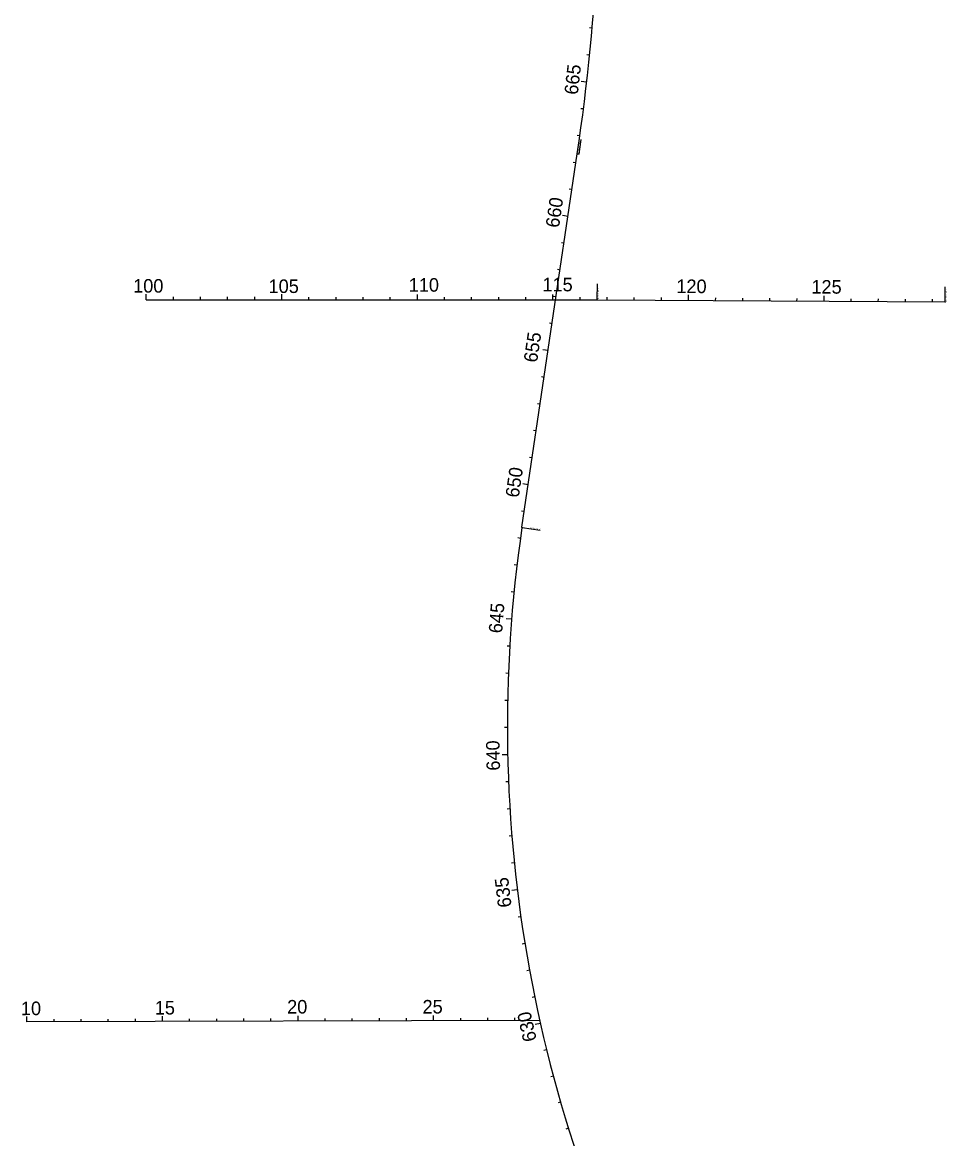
# Model space of a CAD drawing. Extents: x 448091 to 665917, y 1461380 to 1587607.
# Drawn here: x 474927 to 478337, y 1578644 to 1582760 of the extents above; entities that cross this region are included whole.
import ezdxf

# ---------------------------------------------------------------- set-up
doc = ezdxf.new("R2010")
doc.units = 0
for name, color, linetype in [('AttenuatorTM', 7, 'Continuous'), ('BillboardVeg', 7, 'Continuous'), ('BillboardZone', 7, 'Continuous'), ('BLSurvey_dp', 7, 'Continuous'), ('BLSurveyCntrl_ep', 7, 'Continuous'), ('BLSurveyField_ep', 7, 'Continuous'), ('BLSurveySymbl_ep', 7, 'Continuous'), ('BoxCulvert_ep', 7, 'Continuous')]:
    doc.layers.add(name, color=color, linetype=linetype)

msp = doc.modelspace()

# ---------------------------------------------------------------- linework, layer by layer
at = {"layer": 'AttenuatorTM'}
for p, q in [((476980.8, 1582273.8), (476988.8, 1582327.9)), ((476980.8, 1582273.8), (476974.7, 1582274.7)), ((477048, 1581737.8), (477048.1, 1581796.3)), ((478330.9, 1581729.9), (478331.3, 1581784.9)), ((476770.9, 1580898.1), (476836.7, 1580888.3))]:
    msp.add_line(p, q, dxfattribs=at)
for centre in [(476974, 1582274.8), (477048, 1581737.1), (478330.9, 1581729.1), (476770.1, 1580898.2)]:
    msp.add_circle(centre, 0.75, dxfattribs=at)
at = {"layer": 'BillboardVeg'}
msp.add_line((476770.1, 1580898.2), (476974, 1582274.8), dxfattribs=at)
for centre, radius, start, end in [((469060.2, 1583446.5), 8000, 351.57825, 2.73207), ((481716.2, 1580165.9), 5000, 171.5783, 209.1468)]:
    msp.add_arc(centre, radius, start, end, dxfattribs=at)
at = {"layer": 'BLSurvey_dp'}
for p, q in [((477028.9, 1582738.9), (477018.9, 1582739.8)), ((477019.4, 1582639.4), (477009.5, 1582640.4)), ((477008.7, 1582539.9), (476988.8, 1582542.2)), ((476996.7, 1582440.7), (476986.8, 1582441.9)), ((476983.6, 1582341.5), (476973.7, 1582342.9)), ((476969.2, 1582242.6), (476959.3, 1582244)), ((476954.5, 1582143.7), (476944.7, 1582145.1)), ((476939.9, 1582044.7), (476920.1, 1582047.7)), ((476925.3, 1581945.8), (476915.4, 1581947.3)), ((476910.6, 1581846.9), (476900.7, 1581848.4)), ((476896, 1581748), (476886.1, 1581749.4)), ((476881.3, 1581649), (476871.4, 1581650.5)), ((476866.7, 1581550.1), (476846.9, 1581553.1)), ((476852, 1581451.2), (476842.1, 1581452.7)), ((476837.4, 1581352.3), (476827.5, 1581353.7)), ((476822.7, 1581253.4), (476812.8, 1581254.8)), ((476808.1, 1581154.4), (476798.2, 1581155.9)), ((476793.4, 1581055.5), (476773.7, 1581058.4)), ((476778.8, 1580956.6), (476768.9, 1580958.1)), ((476764.3, 1580857.6), (476754.4, 1580859)), ((476751.5, 1580758.5), (476741.5, 1580759.7)), ((476740.6, 1580659.1), (476730.7, 1580660.1)), ((476731.7, 1580559.5), (476711.8, 1580561)), ((476724.9, 1580459.7), (476714.9, 1580460.3)), ((476720, 1580359.8), (476710, 1580360.2)), ((476717.1, 1580259.9), (476707.1, 1580260.1)), ((476716.2, 1580159.9), (476706.2, 1580159.9)), ((476717.4, 1580059.9), (476697.4, 1580059.5)), ((476720.5, 1579959.9), (476710.5, 1579959.5)), ((476725.6, 1579860.1), (476715.6, 1579859.5)), ((476732.7, 1579760.3), (476722.7, 1579759.5)), ((476741.8, 1579660.7), (476731.9, 1579659.7)), ((476752.9, 1579561.4), (476733.1, 1579558.9)), ((476766, 1579462.2), (476756.1, 1579460.8)), ((476781.1, 1579363.4), (476771.2, 1579361.8)), ((476798.1, 1579264.8), (476788.3, 1579263)), ((476817.1, 1579166.6), (476807.3, 1579164.6)), ((476838.1, 1579068.9), (476818.5, 1579064.5)), ((476861, 1578971.5), (476851.3, 1578969.1)), ((476885.8, 1578874.7), (476876.2, 1578872.1)), ((476912.6, 1578778.3), (476903, 1578775.6)), ((476941.3, 1578682.5), (476931.8, 1578679.6))]:
    msp.add_line(p, q, dxfattribs=at)
at = {"layer": 'BLSurveyCntrl_ep'}
for p, q in [((475384.5, 1581737.6), (477048, 1581737.1)), ((477048, 1581737.1), (478330.9, 1581729.1))]:
    msp.add_line(p, q, dxfattribs=at)
at = {"layer": 'BLSurveyField_ep'}
for p, q in [((475384.5, 1581737.6), (475384.5, 1581757.6)), ((475484.5, 1581737.6), (475484.5, 1581747.6)), ((475584.5, 1581737.5), (475584.5, 1581747.5)), ((475684.5, 1581737.5), (475684.5, 1581747.5)), ((475784.5, 1581737.5), (475784.5, 1581747.5)), ((475884.5, 1581737.4), (475884.5, 1581757.4)), ((475984.5, 1581737.4), (475984.5, 1581747.4)), ((476084.5, 1581737.4), (476084.5, 1581747.4)), ((476184.5, 1581737.3), (476184.5, 1581747.3)), ((476284.5, 1581737.3), (476284.5, 1581747.3)), ((476384.5, 1581737.3), (476384.5, 1581757.3)), ((476484.5, 1581737.2), (476484.5, 1581747.2)), ((476584.5, 1581737.2), (476584.5, 1581747.2)), ((476684.5, 1581737.2), (476684.5, 1581747.2)), ((476784.5, 1581737.1), (476784.5, 1581747.1)), ((476884.5, 1581737.1), (476884.5, 1581757.1)), ((476984.5, 1581737.1), (476984.5, 1581747.1)), ((477084.5, 1581736.8), (477084.5, 1581746.8)), ((477184.4, 1581736.2), (477184.5, 1581746.2)), ((477284.4, 1581735.6), (477284.5, 1581745.6)), ((477384.4, 1581735), (477384.6, 1581755)), ((477484.4, 1581734.4), (477484.5, 1581744.4)), ((477584.4, 1581733.7), (477584.5, 1581743.7)), ((477684.4, 1581733.1), (477684.5, 1581743.1)), ((477784.4, 1581732.5), (477784.5, 1581742.5)), ((477884.4, 1581731.9), (477884.6, 1581751.9)), ((477984.4, 1581731.3), (477984.5, 1581741.3)), ((478084.4, 1581730.7), (478084.5, 1581740.7)), ((478184.4, 1581730), (478184.5, 1581740)), ((478284.4, 1581729.4), (478284.5, 1581739.4))]:
    msp.add_line(p, q, dxfattribs=at)
at = {"layer": 'BoxCulvert_ep'}
for p, q in [((474944.2, 1579074.4), (474944.1, 1579094.4)), ((476835.7, 1579079.5), (474944.2, 1579074.4)), ((475044.2, 1579074.6), (475044.2, 1579084.6)), ((475144.2, 1579074.9), (475144.2, 1579084.9)), ((475244.2, 1579075.2), (475244.2, 1579085.2)), ((475344.2, 1579075.5), (475344.2, 1579085.5)), ((475444.2, 1579075.7), (475444.1, 1579095.7)), ((475544.2, 1579076), (475544.2, 1579086)), ((475644.2, 1579076.3), (475644.2, 1579086.3)), ((475744.2, 1579076.6), (475744.2, 1579086.6)), ((475844.2, 1579076.8), (475844.2, 1579086.8)), ((475944.2, 1579077.1), (475944.1, 1579097.1)), ((476044.2, 1579077.4), (476044.2, 1579087.4)), ((476144.2, 1579077.7), (476144.2, 1579087.7)), ((476244.2, 1579077.9), (476244.2, 1579087.9)), ((476344.2, 1579078.2), (476344.2, 1579088.2)), ((476444.2, 1579078.5), (476444.1, 1579098.5)), ((476544.2, 1579078.7), (476544.2, 1579088.7)), ((476644.2, 1579079), (476644.2, 1579089)), ((476744.2, 1579079.3), (476744.2, 1579089.3))]:
    msp.add_line(p, q, dxfattribs=at)

# ---------------------------------------------------------------- texts
at = {"layer": 'AttenuatorTM'}
for s, rotation, p in [('PC STA. 662+32.58', 81.5783, (476979.7, 1582275.9)), ('PI STA. 116+63.58', 89.9821, (477052.8, 1581739.5)), ('POT STA. 129+46.49', 89.6458, (478336.2, 1581730.4)), ('PT STA. 648+40.95', 171.5783, (476837.7, 1580893.1))]:
    msp.add_text(s, height=3.5, rotation=rotation, dxfattribs=at).set_placement(p)
at = {"layer": 'BillboardZone'}
for s, rotation, p in [('665', 83.4935, (476975.7, 1582491.5)), ('660', 81.5783, (476906.4, 1582000.6)), ('655', 81.5783, (476825.4, 1581503.8)), ('650', 81.5783, (476758, 1581005.6)), ('645', 85.4852, (476696.8, 1580506.3)), ('640', 91.2148, (476689.5, 1580001.5)), ('635', 96.9444, (476732.1, 1579499.4)), ('630', 102.674, (476824.9, 1579007.7))]:
    msp.add_text(s, height=50, rotation=rotation, dxfattribs=at).set_placement(p)
at = {"layer": 'BLSurveySymbl_ep'}
for s, rotation, p in [('100', 359.9821, (475336, 1581763.6)), ('105', 359.9821, (475835.4, 1581762.3)), ('110', 359.9821, (476352.4, 1581767.1)), ('115', 359.9821, (476845.6, 1581768.4)), ('120', 359.6458, (477339.4, 1581762.3)), ('125', 359.6458, (477837.5, 1581760.3))]:
    msp.add_text(s, height=50, rotation=rotation, dxfattribs=at).set_placement(p)
at = {"layer": 'BoxCulvert_ep'}
for s, p in [('10', (474922.1, 1579099.4)), ('15', (475415.8, 1579101.7)), ('20', (475904, 1579105.3)), ('25', (476403.4, 1579105.4))]:
    msp.add_text(s, height=50, rotation=0.1568, dxfattribs=at).set_placement(p)

doc.saveas('drawing.dxf')
